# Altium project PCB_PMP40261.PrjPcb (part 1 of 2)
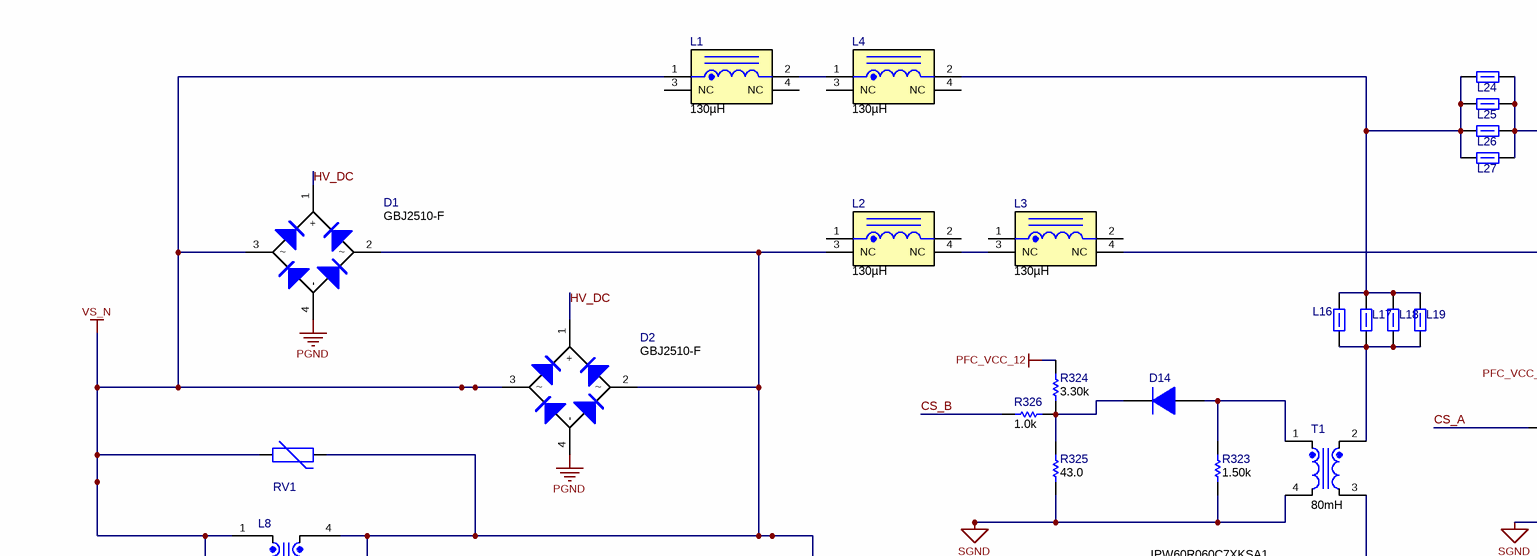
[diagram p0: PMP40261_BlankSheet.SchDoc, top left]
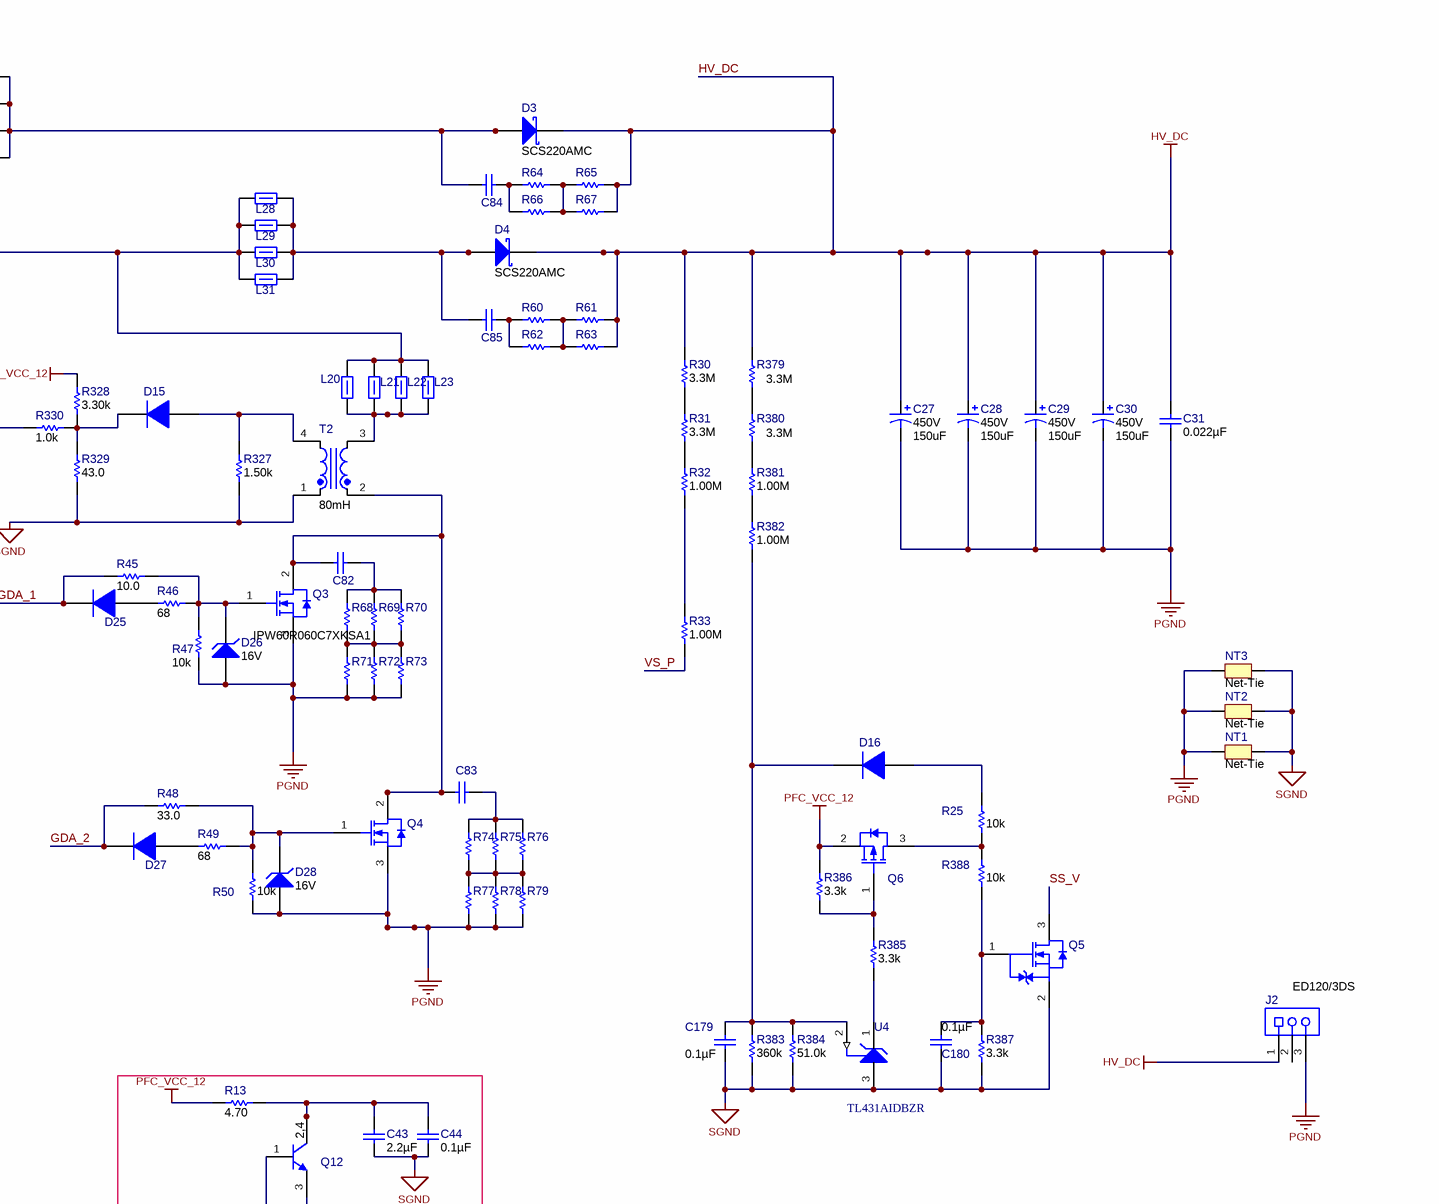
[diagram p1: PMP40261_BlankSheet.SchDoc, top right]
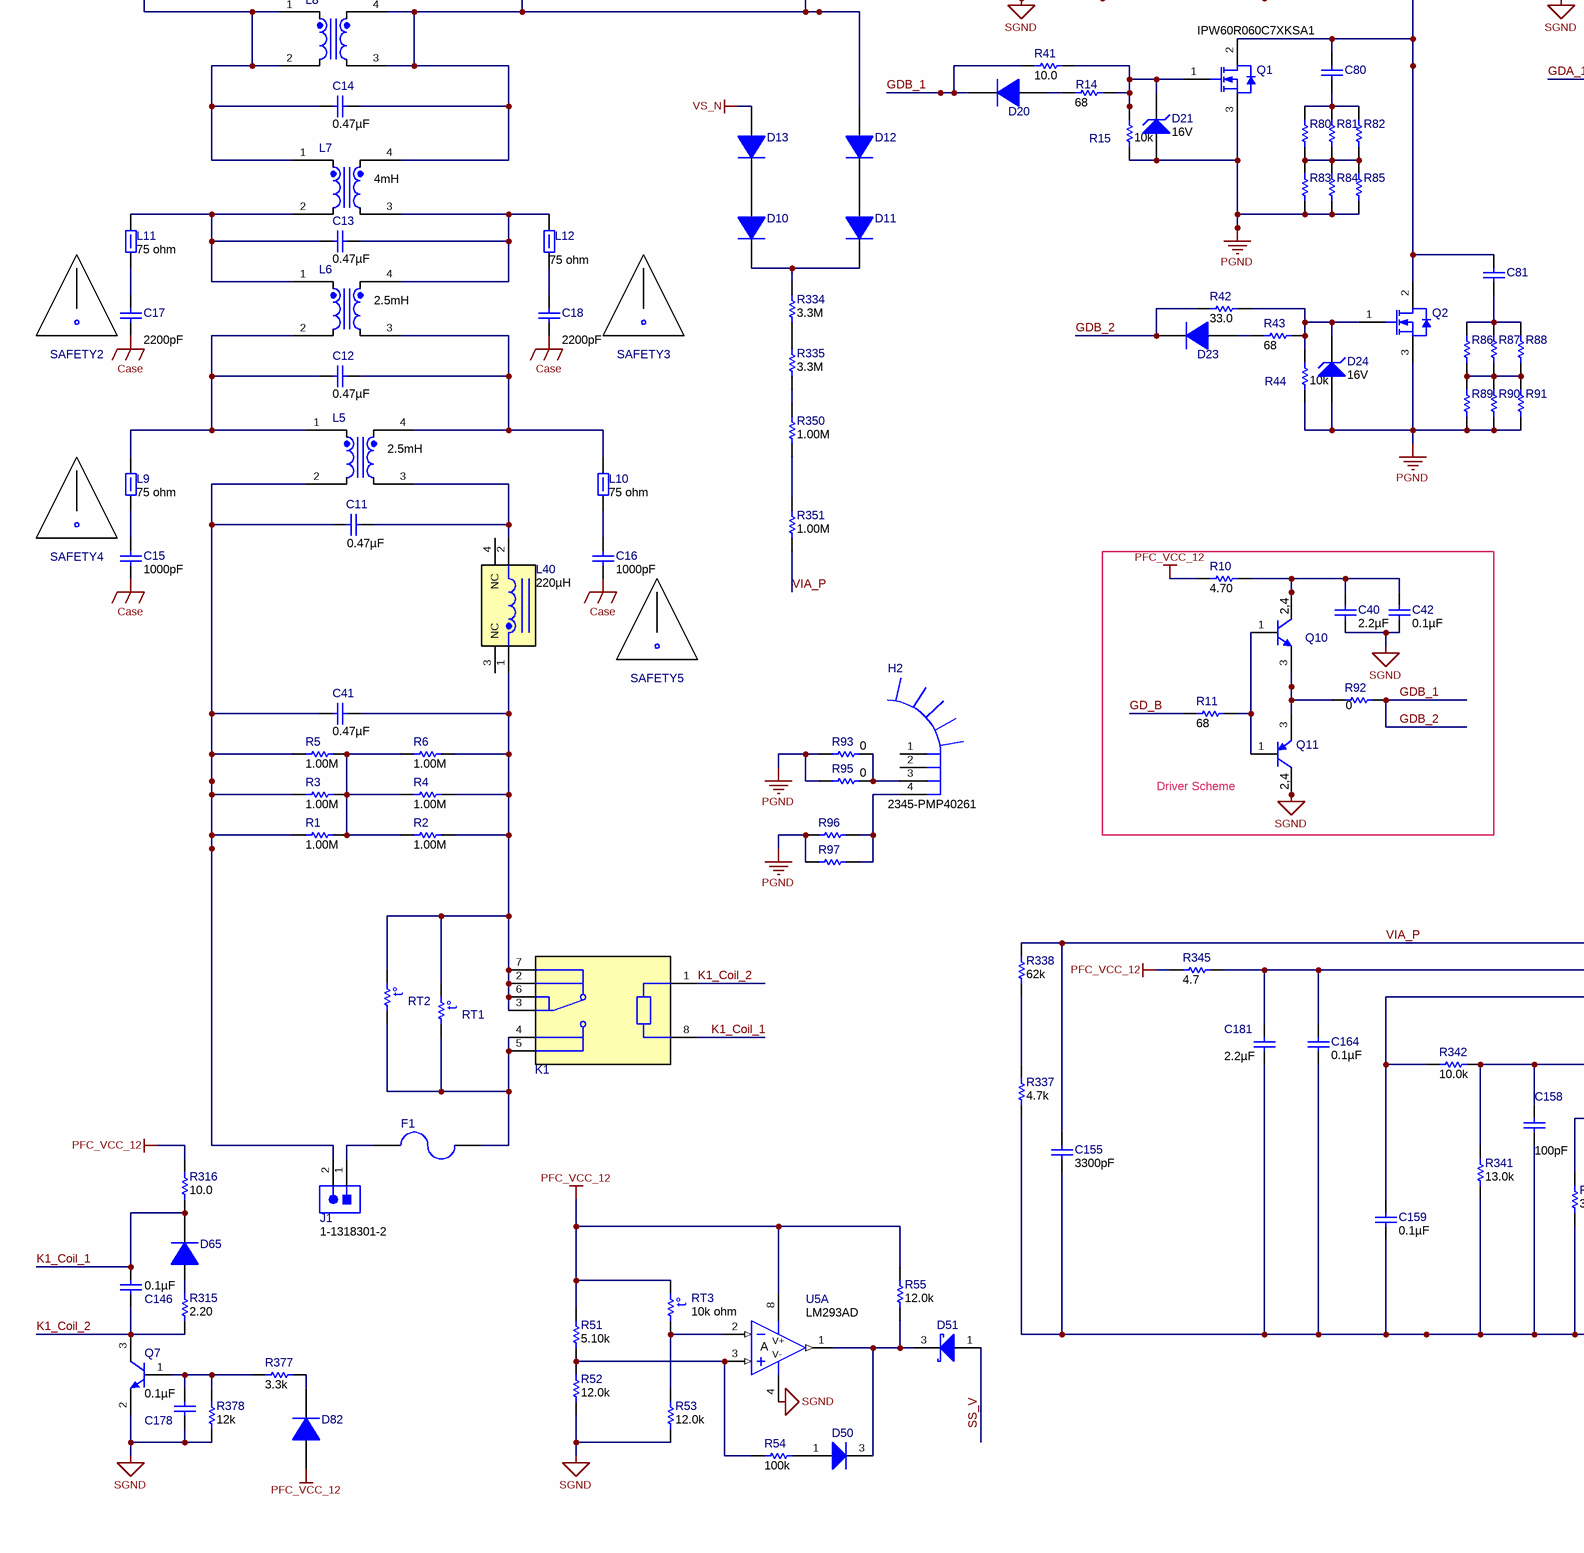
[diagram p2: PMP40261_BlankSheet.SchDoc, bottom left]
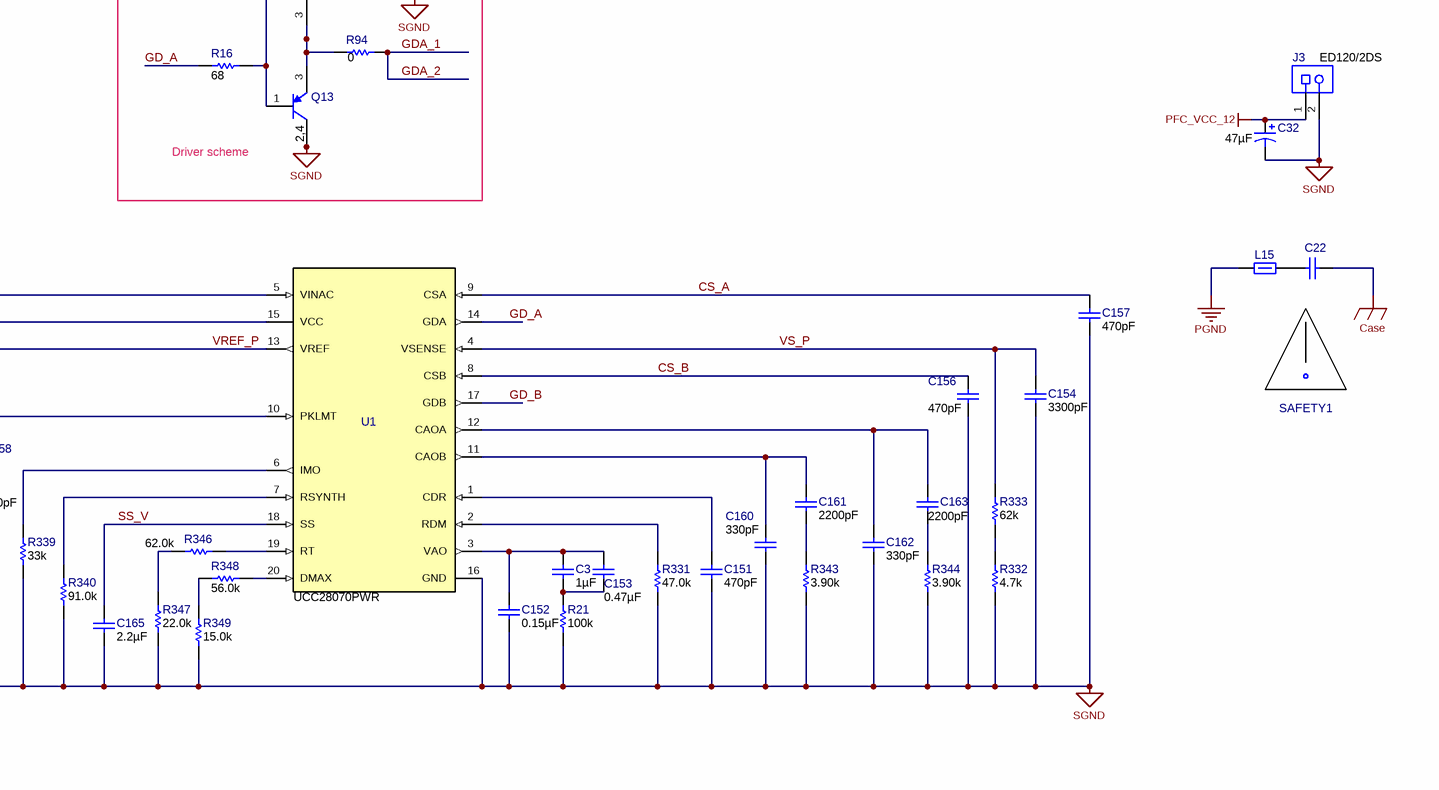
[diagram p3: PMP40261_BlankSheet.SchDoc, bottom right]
CopyrightYear: 2017; PCB_Layout: Who did the Layout?; PCB_Rev: E1; PRJ_Customer: Public Release; PRJ_Engineer: San Chen; PRJ_Number: PMP40261; PRJ_Title: 800W High Efficiency Bridgeless PFC Reference Design; SCH_Rev: E1; TechSupport: http://www.ti.com/support; TID: N/A
1 sheet, 242 parts. Net scope: global (net labels, ports and power ports of the same name join across sheets).
Board file: PMP40261B_pcb.PCBDOC

## Sheet PMP40261_BlankSheet.SchDoc
size A2; Date: Not shown in title block; ApprovedBy: Not shown in title block; CheckedBy: Not shown in title block; Author: Not shown in title block; CompanyName: Not shown in title block; Engineer: San Chen; Organization: Not shown in title block; Address1: Not shown in title block; Address2: Not shown in title block; Address3: Not shown in title block; Address4: Not shown in title block; DocumentNumber: 1; Revision: Use project parameter SCH_Rev; SheetNumber: 1; SheetTotal: 1; PageSetup: Record=PageOptions¦CenterHorizontal=True¦CenterVertical=True¦PrintScale=1.00¦XCorrection=1.00¦YCorrection=1.00¦PrintKind=0¦BorderSize=5000000¦LeftOffset=0¦BottomOffset=0¦Orientation=2¦PaperLength=1000¦PaperWidth=1000¦Scale=100¦PaperSource=15¦PrintQuality=600¦MediaType=1¦DitherType=10¦PaperKind=Letter¦PrintScaleMode=1

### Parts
C3  ValueDisplayed: 1µF  [0603]  (hidden comment: UMK107AB7105KA-T)
C11  ValueDisplayed: 0.47µF  [Kemet_1800x850x1450]  (hidden comment: R46KI347050P0K)
C12  ValueDisplayed: 0.47µF  [Kemet_1800x850x1450]  (hidden comment: R46KI347050P0K)
C13  ValueDisplayed: 0.47µF  [Kemet_1800x850x1450]  (hidden comment: R46KI347050P0K)
C14  ValueDisplayed: 0.47µF  [Kemet_1800x850x1450]  (hidden comment: R46KI347050P0K)
C15  ValueDisplayed: 1000pF  [DE_800x1200x800]  (hidden comment: DE1E3KX102MA5BA01)
C16  ValueDisplayed: 1000pF  [DE_800x1200x800]  (hidden comment: DE1E3KX102MA5BA01)
C17  ValueDisplayed: 2200pF  [CAPRD500W60D800H850]  (hidden comment: DE2E3KY222MA2BM01)
C18  ValueDisplayed: 2200pF  [CAPRD500W60D800H850]  (hidden comment: DE2E3KY222MA2BM01)
C22  DE1B3KX221KN4AP01F  [DE1_87]  (value not drawn)
C27  VDC_V: 450V  ValueDisplayed: 150uF  [BXW_1800x4500_HorizontalDown]  (hidden comment: 450BXW150MEFC18X45)
C28  VDC_V: 450V  ValueDisplayed: 150uF  [BXW_1800x4500_HorizontalDown]  (hidden comment: 450BXW150MEFC18X45)
C29  VDC_V: 450V  ValueDisplayed: 150uF  [BXW_1800x4500_HorizontalDown]  (hidden comment: 450BXW150MEFC18X45)
C30  VDC_V: 450V  ValueDisplayed: 150uF  [BXW_1800x4500_HorizontalDown]  (hidden comment: 450BXW150MEFC18X45)
C31  ValueDisplayed: 0.022µF  [ECWF_L_1250x620x1050]  (hidden comment: ECWF6223JL)
C32  ValueDisplayed: 47µF  [FC_630x1120]  (hidden comment: EEU-FC1V470)
C40  ValueDisplayed: 2.2µF  [0805_HV]  (hidden comment: C2012X7R1H225K125AC)
C41  ValueDisplayed: 0.47µF  [Kemet_1800x850x1450]  (hidden comment: R46KI347050P0K)
C42  ValueDisplayed: 0.1µF  [0603]  (hidden comment: GRM188R71H104KA93D)
C43  ValueDisplayed: 2.2µF  [0805_HV]  (hidden comment: C2012X7R1H225K125AC)
C44  ValueDisplayed: 0.1µF  [0603]  (hidden comment: GRM188R71H104KA93D)
C80  CK45-R3AD101KAGRA  [CK45_600x500x1000]  (value not drawn)
C81  CK45-R3AD101KAGRA  [CK45_600x500x1000]  (value not drawn)
C82  CK45-R3AD101KAGRA  [CK45_600x500x1000]  (value not drawn)
C83  CK45-R3AD101KAGRA  [CK45_600x500x1000]  (value not drawn)
C84  CK45-R3AD101KAGRA  [CK45_600x500x1000]  (value not drawn)
C85  CK45-R3AD101KAGRA  [CK45_600x500x1000]  (value not drawn)
C146  ValueDisplayed: 0.1µF  [0603]  (hidden comment: GRM188R71H104KA93D)
C151  ValueDisplayed: 470pF  [0603]  (hidden comment: 06031C471KAT2A)
C152  ValueDisplayed: 0.15µF  [0603]  (hidden comment: C1608X7R1E154K080AA)
C153  ValueDisplayed: 0.47µF  [0603]  (hidden comment: C1608X7R1H474K080AC)
C154  ValueDisplayed: 3300pF  [0603]  (hidden comment: 06031C332JAT2A)
C155  ValueDisplayed: 3300pF  [0603]  (hidden comment: 06031C332JAT2A)
C156  ValueDisplayed: 470pF  [0603]  (hidden comment: 06031C471JAT2A)
C157  ValueDisplayed: 470pF  [0603]  (hidden comment: 06031C471JAT2A)
C158  ValueDisplayed: 100pF  [0603]  (hidden comment: 0603ZC101KAT2A)
C159  ValueDisplayed: 0.1µF  [0603]  (hidden comment: GRM188R71H104KA93D)
C160  ValueDisplayed: 330pF  [0603]  (hidden comment: C0603C331K5RACTU)
C161  ValueDisplayed: 2200pF  [0603]  (hidden comment: C0603C222K5RACTU)
C162  ValueDisplayed: 330pF  [0603]  (hidden comment: C0603C331K5RACTU)
C163  ValueDisplayed: 2200pF  [0603]  (hidden comment: C0603C222K5RACTU)
C164  ValueDisplayed: 0.1µF  [0603]  (hidden comment: GRM188R71H104KA93D)
C165  ValueDisplayed: 2.2µF  [0805_HV]  (hidden comment: C2012X7R1H225K125AC)
C178  ValueDisplayed: 0.1µF  [0603]  (hidden comment: GRM188R71H104KA93D)
C179  ValueDisplayed: 0.1µF  [0603]  (hidden comment: GRM188R71H104KA93D)
C180  ValueDisplayed: 0.1µF  [0603]  (hidden comment: GRM188R71H104KA93D)
C181  ValueDisplayed: 2.2µF  [0805_HV]  (hidden comment: C2012X7R1H225K125AC)
D1  GBJ2510-F  [GBJ]
D2  GBJ2510-F  [GBJ]
D3  SCS220AMC  [TO-220-2_HORIZ_MH]
D4  SCS220AMC  [TO-220-2_HORIZ_MH]
D10  US1J-13-F  [SMA]  (value not drawn)
D11  US1J-13-F  [SMA]  (value not drawn)
D12  US1J-13-F  [SMA]  (value not drawn)
D13  US1J-13-F  [SMA]  (value not drawn)
D14  RF071M2S  [SOD-123]  (value not drawn)
D15  RF071M2S  [SOD-123]  (value not drawn)
D16  1N4148W-7-F  [SOD-123]  (value not drawn)
D20  1N4148W-7-F  [SOD-123]  (value not drawn)
D21  value 16V  [SOD-123]  (hidden comment: BZT52B16-HE3-08)
D23  1N4148W-7-F  [SOD-123]  (value not drawn)
D24  value 16V  [SOD-123]  (hidden comment: BZT52B16-HE3-08)
D25  1N4148W-7-F  [SOD-123]  (value not drawn)
D26  value 16V  [SOD-123]  (hidden comment: BZT52B16-HE3-08)
D27  1N4148W-7-F  [SOD-123]  (value not drawn)
D28  value 16V  [SOD-123]  (hidden comment: BZT52B16-HE3-08)
D50  BAS16LT1G  [SOT-23]  (value not drawn)
D51  BAT54-7-F  [SOT-23]  (value not drawn)
D65  1N4148W-7-F  [SOD-123]  (value not drawn)
D82  1N4148W-7-F  [SOD-123]  (value not drawn)
F1  HDP500 12A250V  [Fuse_HDP500]  (value not drawn)
H2  2345-PMP40261  [2345-PMP40261]
J1  1-1318301-2  [Amp_1-1318301-2]
J2  ED120/3DS  [On-Shore_ED120_3DS]
J3  ED120/2DS  [On-Shore_ED120_2DS]
K1  G2RL-14-E DC12  [RELAY_G2RL-14-E]  (value not drawn)
L1  ValueDisplayed: 130µH  [CY0239-AL]  (hidden comment: CY0239-BL)
L2  ValueDisplayed: 130µH  [CY0239-AL]  (hidden comment: CY0239-BL)
L3  ValueDisplayed: 130µH  [CY0239-AL]  (hidden comment: CY0239-BL)
L4  ValueDisplayed: 130µH  [CY0239-AL]  (hidden comment: CY0239-BL)
L5  ValueDisplayed: 2.5mH  [Wurth_750343684]  (hidden comment: 750343684)
L6  ValueDisplayed: 2.5mH  [Wurth_750343684]  (hidden comment: 750343684)
L7  ValueDisplayed: 4mH  [Wurth_750343785]  (hidden comment: 7448041104)
L8  0  [Wurth_750343684]  (value not drawn)
L9  ValueDisplayed: 75 ohm  [28L0138]  (hidden comment: 28L0138-10R-10)
L10  ValueDisplayed: 75 ohm  [28L0138]  (hidden comment: 28L0138-10R-10)
L11  ValueDisplayed: 75 ohm  [28L0138]  (hidden comment: 28L0138-10R-10)
L12  ValueDisplayed: 75 ohm  [28L0138]  (hidden comment: 28L0138-10R-10)
L15  28L0138-10R-10  [28L0138]  (value not drawn)
L16  28L0138-10R-10  [28L0138]  (value not drawn)
L17  28L0138-10R-10  [28L0138]  (value not drawn)
L18  28L0138-10R-10  [28L0138]  (value not drawn)
L19  28L0138-10R-10  [28L0138]  (value not drawn)
L20  28L0138-10R-10  [28L0138]  (value not drawn)
L21  28L0138-10R-10  [28L0138]  (value not drawn)
L22  28L0138-10R-10  [28L0138]  (value not drawn)
L23  28L0138-10R-10  [28L0138]  (value not drawn)
L24  28L0138-10R-10  [28L0138]  (value not drawn)
L25  28L0138-10R-10  [28L0138]  (value not drawn)
L26  28L0138-10R-10  [28L0138]  (value not drawn)
L27  28L0138-10R-10  [28L0138]  (value not drawn)
L28  28L0138-10R-10  [28L0138]  (value not drawn)
L29  28L0138-10R-10  [28L0138]  (value not drawn)
L30  28L0138-10R-10  [28L0138]  (value not drawn)
L31  28L0138-10R-10  [28L0138]  (value not drawn)
L40  ValueDisplayed: 220µH  [CY0203-BL]  (hidden comment: CY0203-BL)
NT1  Net-Tie  [Net-Tie_10mil]  (net tie, no BOM)
NT2  Net-Tie  [Net-Tie_10mil]  (net tie, no BOM)
NT3  Net-Tie  [Net-Tie_10mil]  (net tie, no BOM)
Q1  IPW60R060C7XKSA1  [TO-247_Horizontal_Down_1]
Q2  IPW60R060C7XKSA1  [TO-247_Horizontal_Down_1]  (value not drawn)
Q3  IPW60R060C7XKSA1  [TO-247_Horizontal_Down_1]
Q4  IPW60R060C7XKSA1  [TO-247_Horizontal_Down_1]  (value not drawn)
Q5  2N7002K-T1-E3  [SOT-23]  (value not drawn)
Q6  AO3401A  [SOT-23L]  (value not drawn)
Q7  MMBT4401-7-F  [SOT-23]  (value not drawn)
Q10  PBSS4250X,115  [SOT-89-3]  (value not drawn)
Q11  PBSS5250X,115  [SOT-89-3]  (value not drawn)
Q12  PBSS4250X,115  [SOT-89-3]  (value not drawn)
Q13  PBSS5250X,115  [SOT-89-3]  (value not drawn)
R1  ValueDisplayed: 1.00M  [1206]  (hidden comment: CRCW12061M00FKEA)
R2  ValueDisplayed: 1.00M  [1206]  (hidden comment: CRCW12061M00FKEA)
R3  ValueDisplayed: 1.00M  [1206]  (hidden comment: CRCW12061M00FKEA)
R4  ValueDisplayed: 1.00M  [1206]  (hidden comment: CRCW12061M00FKEA)
R5  ValueDisplayed: 1.00M  [1206]  (hidden comment: CRCW12061M00FKEA)
R6  ValueDisplayed: 1.00M  [1206]  (hidden comment: CRCW12061M00FKEA)
R10  ValueDisplayed: 4.70  [1206]  (hidden comment: RC1206FR-074R7L)
R11  ValueDisplayed: 68  [1206]  (hidden comment: CRCW120668R0JNEA)
R13  ValueDisplayed: 4.70  [1206]  (hidden comment: RC1206FR-074R7L)
R14  ValueDisplayed: 68  [1206]  (hidden comment: CRCW120668R0JNEA)
R15  ValueDisplayed: 10k  [0805_HV]  (hidden comment: CRCW080510K0JNEA)
R16  ValueDisplayed: 68  [1206]  (hidden comment: CRCW120668R0JNEA)
R21  ValueDisplayed: 100k  [0603]  (hidden comment: CRCW0603100KFKEA)
R25  ValueDisplayed: 10k  [0805_HV]  (hidden comment: CRCW080510K0JNEA)
R30  ValueDisplayed: 3.3M  [1206]  (hidden comment: RC1206FR-073M3L)
R31  ValueDisplayed: 3.3M  [1206]  (hidden comment: RC1206FR-073M3L)
R32  ValueDisplayed: 1.00M  [1206]  (hidden comment: CRCW12061M00FKEA)
R33  ValueDisplayed: 1.00M  [1206]  (hidden comment: CRCW12061M00FKEA)
R41  ValueDisplayed: 10.0  [1206]  (hidden comment: RC1206FR-0710RL)
R42  ValueDisplayed: 33.0  [1206]  (hidden comment: RC1206FR-0733RL)
R43  ValueDisplayed: 68  [1206]  (hidden comment: CRCW120668R0JNEA)
R44  ValueDisplayed: 10k  [0805_HV]  (hidden comment: CRCW080510K0JNEA)
R45  ValueDisplayed: 10.0  [1206]  (hidden comment: RC1206FR-0710RL)
R46  ValueDisplayed: 68  [1206]  (hidden comment: CRCW120668R0JNEA)
R47  ValueDisplayed: 10k  [0805_HV]  (hidden comment: CRCW080510K0JNEA)
R48  ValueDisplayed: 33.0  [1206]  (hidden comment: RC1206FR-0733RL)
R49  ValueDisplayed: 68  [1206]  (hidden comment: CRCW120668R0JNEA)
R50  ValueDisplayed: 10k  [0805_HV]  (hidden comment: CRCW080510K0JNEA)
R51  ValueDisplayed: 5.10k  [0603]  (hidden comment: RC0603FR-075K1L)
R52  ValueDisplayed: 12.0k  [0603]  (hidden comment: RC0603FR-0712KL)
R53  ValueDisplayed: 12.0k  [0603]  (hidden comment: RC0603FR-0712KL)
R54  ValueDisplayed: 100k  [0603]  (hidden comment: CRCW0603100KFKEA)
R55  ValueDisplayed: 12.0k  [0603]  (hidden comment: RC0603FR-0712KL)
R60  ERJ-8ENF39R0V  [1206]  (value not drawn)
R61  ERJ-8ENF39R0V  [1206]  (value not drawn)
R62  ERJ-8ENF39R0V  [1206]  (value not drawn)
R63  ERJ-8ENF39R0V  [1206]  (value not drawn)
R64  ERJ-8ENF39R0V  [1206]  (value not drawn)
R65  ERJ-8ENF39R0V  [1206]  (value not drawn)
R66  ERJ-8ENF39R0V  [1206]  (value not drawn)
R67  ERJ-8ENF39R0V  [1206]  (value not drawn)
R68  ERJ-8ENF39R0V  [1206]  (value not drawn)
R69  ERJ-8ENF39R0V  [1206]  (value not drawn)
R70  ERJ-8ENF39R0V  [1206]  (value not drawn)
R71  ERJ-8ENF39R0V  [1206]  (value not drawn)
R72  ERJ-8ENF39R0V  [1206]  (value not drawn)
R73  ERJ-8ENF39R0V  [1206]  (value not drawn)
R74  ERJ-8ENF39R0V  [1206]  (value not drawn)
R75  ERJ-8ENF39R0V  [1206]  (value not drawn)
R76  ERJ-8ENF39R0V  [1206]  (value not drawn)
R77  ERJ-8ENF39R0V  [1206]  (value not drawn)
R78  ERJ-8ENF39R0V  [1206]  (value not drawn)
R79  ERJ-8ENF39R0V  [1206]  (value not drawn)
R80  ERJ-8ENF39R0V  [1206]  (value not drawn)
R81  ERJ-8ENF39R0V  [1206]  (value not drawn)
R82  ERJ-8ENF39R0V  [1206]  (value not drawn)
R83  ERJ-8ENF39R0V  [1206]  (value not drawn)
R84  ERJ-8ENF39R0V  [1206]  (value not drawn)
R85  ERJ-8ENF39R0V  [1206]  (value not drawn)
R86  ERJ-8ENF39R0V  [1206]  (value not drawn)
R87  ERJ-8ENF39R0V  [1206]  (value not drawn)
R88  ERJ-8ENF39R0V  [1206]  (value not drawn)
R89  ERJ-8ENF39R0V  [1206]  (value not drawn)
R90  ERJ-8ENF39R0V  [1206]  (value not drawn)
R91  ERJ-8ENF39R0V  [1206]  (value not drawn)
R92  ValueDisplayed: 0  [5108]  (hidden comment: 5108)
R93  ValueDisplayed: 0  [5108]  (hidden comment: 5108)
R94  ValueDisplayed: 0  [5108]  (hidden comment: 5108)
R95  ValueDisplayed: 0  [5108]  (hidden comment: 5108)
R96  5108  [5108]  (value not drawn)
R97  5108  [5108]  (value not drawn)
R315  ValueDisplayed: 2.20  [1206]  (hidden comment: RC1206FR-072R2L)
R316  ValueDisplayed: 10.0  [1206]  (hidden comment: RC1206FR-0710RL)
R323  ValueDisplayed: 1.50k  [1206]  (hidden comment: CRCW12061K50FKEA)
R324  ValueDisplayed: 3.30k  [0603]  (hidden comment: RC0603FR-073K3L)
R325  ValueDisplayed: 43.0  [1206]  (hidden comment: RC1206FR-0743RL)
R326  ValueDisplayed: 1.0k  [0805_HV]  (hidden comment: CRCW08051K00JNEA)
R327  ValueDisplayed: 1.50k  [1206]  (hidden comment: CRCW12061K50FKEA)
R328  ValueDisplayed: 3.30k  [0603]  (hidden comment: RC0603FR-073K3L)
R329  ValueDisplayed: 43.0  [1206]  (hidden comment: RC1206FR-0743RL)
R330  ValueDisplayed: 1.0k  [0805_HV]  (hidden comment: CRCW08051K00JNEA)
R331  ValueDisplayed: 47.0k  [0603]  (hidden comment: CRCW060347K0FKEA)
R332  ValueDisplayed: 4.7k  [0805_HV]  (hidden comment: KTR10EZPF4701)
R333  ValueDisplayed: 62k  [0805_HV]  (hidden comment: KTR10EZPF6202)
R334  ValueDisplayed: 3.3M  [1206]  (hidden comment: RC1206FR-073M3L)
R335  ValueDisplayed: 3.3M  [1206]  (hidden comment: RC1206FR-073M3L)
R337  ValueDisplayed: 4.7k  [0805_HV]  (hidden comment: KTR10EZPF4701)
R338  ValueDisplayed: 62k  [0805_HV]  (hidden comment: KTR10EZPF6202)
R339  ValueDisplayed: 33k  [0603]  (hidden comment: RC0603FR-0724KL)
R340  ValueDisplayed: 91.0k  [0603]  (hidden comment: RC0603FR-0791KL)
R341  ValueDisplayed: 13.0k  [0603]  (hidden comment: CRCW060313K0FKEA)
R342  ValueDisplayed: 10.0k  [0603]  (hidden comment: CRCW060310K0FKEA)
R343  ValueDisplayed: 3.90k  [0603]  (hidden comment: CRCW06033K90FKEA)
R344  ValueDisplayed: 3.90k  [0603]  (hidden comment: CRCW06033K90FKEA)
R345  ValueDisplayed: 4.7  [0805_HV]  (hidden comment: CRCW08054R70JNEA)
R346  ValueDisplayed: 62.0k  [0603]  (hidden comment: RC0603FR-0762KL)
R347  ValueDisplayed: 22.0k  [0603]  (hidden comment: ERJ-3EKF2202V)
R348  ValueDisplayed: 56.0k  [0603]  (hidden comment: RG1608P-563-B-T5)
R349  ValueDisplayed: 15.0k  [0603]  (hidden comment: CRCW060315K0FKEA)
R350  ValueDisplayed: 1.00M  [1206]  (hidden comment: CRCW12061M00FKEA)
R351  ValueDisplayed: 1.00M  [1206]  (hidden comment: CRCW12061M00FKEA)
R377  ValueDisplayed: 3.3k  [0805_HV]  (hidden comment: ERJ-6GEYJ332V)
R378  ValueDisplayed: 12k  [0805_HV]  (hidden comment: CRCW080512K0JNEA)
R379  ValueDisplayed: 3.3M  [1206]  (hidden comment: RC1206FR-073M3L)
R380  ValueDisplayed: 3.3M  [1206]  (hidden comment: RC1206FR-073M3L)
R381  ValueDisplayed: 1.00M  [1206]  (hidden comment: CRCW12061M00FKEA)
R382  ValueDisplayed: 1.00M  [1206]  (hidden comment: CRCW12061M00FKEA)
R383  ValueDisplayed: 360k  [0805_HV]  (hidden comment: CRCW0805360KJNEA)
R384  ValueDisplayed: 51.0k  [1206]  (hidden comment: RC1206FR-0751KL)
R385  ValueDisplayed: 3.3k  [0805_HV]  (hidden comment: ERJ-6GEYJ332V)
R386  ValueDisplayed: 3.3k  [0805_HV]  (hidden comment: ERJ-6GEYJ332V)
R387  ValueDisplayed: 3.3k  [0805_HV]  (hidden comment: ERJ-6GEYJ332V)
R388  ValueDisplayed: 10k  [0805_HV]  (hidden comment: CRCW080510K0JNEA)
RT1  SCK205R0MSBY502  [SCK20_S]  (value not drawn)
RT2  SCK205R0MSBY502  [SCK20_S]  (value not drawn)
RT3  value 10k ohm  [0603]  (hidden comment: NCP18XH103J03RB)
RV1  B72214S0421K101  [TDK_B72214S0421]  (value not drawn)
T1  ValueDisplayed: 80mH  [XFMR_CS4200V-01L]  (hidden comment: CS4200V-01L)
T2  ValueDisplayed: 80mH  [XFMR_CS4200V-01L]  (hidden comment: CS4200V-01L)
U1  UCC28070PWR  [PW0020A_N]
U4  TL431AIDBZR  [DBZ0003A_N]
U5  LM293AD  [D0008A_N]  (part A of 2)

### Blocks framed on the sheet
Driver Scheme: C40 C42 Q10 Q11 R10 R11 R92
Driver scheme: C43 C44 Q12 Q13 R13 R16 R94

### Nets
Case: C15.2 C16.2 C17.2 C18.2 C22.2
HV_DC: C27.1(+) C28.1(+) C29.1(+) C30.1(+) C31.1 D1.1(+) D2.1(+) D3.1(K) D4.1(K) J2.1 R30.2 R61.1 R63.1 R65.1 R67.1 R379.2
PFC_VCC_12: C32.1(+) D82.2(A) J3.1 Q6.2(S) R10.1 R13.1 R51.2 R55.2 R316.2 R324.2 R328.2 R345.1 R386.2 RT3.2 U5.8(V+)
PGND: C27.2(-) C28.2(-) C29.2(-) C30.2(-) C31.2 D1.4(-) D2.4(-) D21.2(A) D24.2(A) D26.2(A) D28.2(A) J2.3 L15.2 NT1.1 NT2.1 NT3.1 Q1.3(S) Q2.3(S) Q3.3(S) Q4.3(S) R15.2 R44.2 R47.2 R50.2 R71.2 R72.2 R73.2 R77.2 R78.2 R79.2 R83.2 R84.2 R85.2 R89.2 R90.2 R91.2 R93.1 R95.1 R96.1 R97.1
SGND: C32.2(-) C40.2 C42.2 C43.2 C44.2 C151.2 C152.2 C154.2 C155.2 C156.2 C157.2 C158.2 C159.2 C160.2 C162.2 C164.2 C165.2 C178.2 C179.2 C180.2 C181.2 J3.2 NT1.2 NT2.2 NT3.2 Q5.2(S) Q7.2(E) Q11.2(C) Q11.4(C) Q13.2(C) Q13.4(C) R21.1 R52.1 R53.1 R323.1 R325.1 R327.1 R329.1 R331.1 R332.1 R337.1 R339.1 R340.1 R341.2 R343.1 R344.1 R347.1 R349.1 R378.1 R383.1 R384.1 R387.1 T1.4 T2.1 U1.16(GND) U4.3(ANODE) U5.4(V-)
VS_N: C14.1 D1.3 D2.3 D13.2(A) L1.1 L7.1 L8.1 L8.2 RV1.1
CS_A: C157.1 R330.2 U1.9(CSA)
CS_B: C156.1 R326.2 U1.8(CSB)
GD_A: R16.1 U1.14(GDA)
GD_B: R11.1 U1.17(GDB)
GDA_1: D25.1(K) D27.1(K) R45.1 R48.1 R94.2  [also labelled GDA_2]
GDB_1: D20.1(K) D23.1(K) R41.1 R42.1 R92.2  [also labelled GDB_2]
K1_Coil_1: C146.1 D65.1(K) K1.8 R316.1
K1_Coil_2: C146.2 K1.1 Q7.3(C) R315.1
SS_V: C165.1 D51.1(A) Q5.3(D) U1.18(SS)
VIA_P: C155.1 R338.2 R351.1 U1.5(VINAC)
VREF_P: C159.1 R342.1 U1.13(VREF)
VS_P: C154.1 R33.1 R333.2 U1.4(VSENSE)
NetC3_1: C3.1 C152.1 C153.1 U1.3(VAO)
NetC3_2: C3.2 C153.2 R21.2
NetC11_1: C11.1 C41.1 J1.2 L5.2 R1.2 R3.2 R5.2
NetC11_2: C11.2 L5.3 L40.2
NetC12_1: C12.1 L5.1 L6.2 L9.2
NetC12_2: C12.2 L5.4 L6.3 L10.2
NetC13_1: C13.1 L6.1 L7.2 L11.2
NetC13_2: C13.2 L6.4 L7.3 L12.2
NetC14_2: C14.2 D1.2 D2.2 D12.2(A) L2.3(NC) L7.4 L8.3 L8.4 RV1.2
NetC15_1: C15.1 L9.1
NetC16_1: C16.1 L10.1
NetC17_1: C17.1 L11.1
NetC18_1: C18.1 L12.1
NetC22_1: C22.1 L15.1
NetC40_1: C40.1 C42.1 Q10.2(C) Q10.4(C) R10.2
NetC41_2: C41.2 K1.2 K1.3 K1.6 K1.7 L40.1 R2.1 R4.1 R6.1 RT1.2 RT2.2
NetC43_1: C43.1 C44.1 Q12.2(C) Q12.4(C) R13.2
NetC80_1: C80.1 C81.1 Q1.2(D) Q2.2(D) T1.3
NetC80_2: C80.2 R80.1 R81.1 R82.1
NetC81_2: C81.2 R86.1 R87.1 R88.1
NetC82_1: C82.1 C83.1 Q3.2(D) Q4.2(D) T2.2
NetC82_2: C82.2 R68.1 R69.1 R70.1
NetC83_2: C83.2 R74.1 R75.1 R76.1
NetC84_1: C84.1 D3.2(A) L24.1 L25.1 L26.1 L27.1
NetC84_2: C84.2 R64.2 R66.2
NetC85_1: C85.1 D4.2(A) L28.1 L29.1 L30.1 L31.1
NetC85_2: C85.2 R60.2 R62.2
NetC151_1: C151.1 U1.1(CDR)
NetC158_1: C158.1 R341.1 R342.2 U1.10(PKLMT)
NetC160_1: C160.1 C161.1 U1.11(CAOB)
NetC161_2: C161.2 R343.2
NetC162_1: C162.1 C163.1 U1.12(CAOA)
NetC163_2: C163.2 R344.2
NetC164_1: C164.1 C181.1 R345.2 U1.15(VCC)
NetC178_1: C178.1 Q7.1(B) R377.1 R378.2
NetC179_1: C179.1 D16.1(K) R382.1 R383.2 R384.2 U4.2(REF)
NetC180_1: C180.1 Q5.1(G) R387.2 R388.2
NetD10_1: D10.1(K) D11.1(K) R334.2
NetD10_2: D10.2(A) D13.1(K)
NetD11_2: D11.2(A) D12.1(K)
NetD14_1: D14.1(K) R324.1 R325.2 R326.1
NetD14_2: D14.2(A) R323.2 T1.1
NetD15_1: D15.1(K) R328.1 R329.2 R330.1
NetD15_2: D15.2(A) R327.2 T2.4
NetD16_2: D16.2(A) R25.1
NetD20_2: D20.2(A) R14.1
NetD21_1: D21.1(K) Q1.1(G) R14.2 R15.1 R41.2
NetD23_2: D23.2(A) R43.1
NetD24_1: D24.1(K) Q2.1(G) R42.2 R43.2 R44.1
NetD25_2: D25.2(A) R46.1
NetD26_1: D26.1(K) Q3.1(G) R45.2 R46.2 R47.1
NetD27_2: D27.2(A) R49.1
NetD28_1: D28.1(K) Q4.1(G) R48.2 R49.2 R50.1
NetD50_1: D50.1(A) R54.1
NetD50_3: D50.3(K) D51.3(K) R55.1 U5.1(OUT)
NetD65_2: D65.2(A) R315.2
NetD82_1: D82.1(K) R377.2
NetF1_1: F1.1 K1.4 K1.5 RT1.1 RT2.1
NetF1_2: F1.2 J1.1
NetH2_3: H2.3 R93.2 R95.2
NetH2_4: H2.4 R96.2 R97.2
NetL1_2: L1.2 L4.1
NetL2_4: L2.4(NC) L3.3(NC)
NetL3_4: L3.4(NC) L20.2 L21.2 L22.2 L23.2 L28.2 L29.2 L30.2 L31.2
NetL4_2: L4.2 L16.2 L17.2 L18.2 L19.2 L24.2 L25.2 L26.2 L27.2
NetL16_1: L16.1 L17.1 L18.1 L19.1 T1.2
NetL20_1: L20.1 L21.1 L22.1 L23.1 T2.3
NetQ6_1: Q6.1(G) R385.2 R386.1
NetQ6_3: Q6.3(D) R25.2 R388.1
NetQ10_1: Q10.1(B) Q11.1(B) R11.2
NetQ10_3: Q10.3(E) Q11.3(E) R92.1
NetQ12_1: Q12.1(B) Q13.1(B) R16.2
NetQ12_3: Q12.3(E) Q13.3(E) R94.1
NetR1_1: R1.1 R2.2 R3.1 R4.2 R5.1 R6.2
NetR30_1: R30.1 R31.2
NetR31_1: R31.1 R32.2
NetR32_1: R32.1 R33.2
NetR51_1: R51.1 R52.2 R54.2 U5.3(IN+)
NetR53_2: R53.2 RT3.1 U5.2(IN-)
NetR60_1: R60.1 R61.2 R62.1 R63.2
NetR64_1: R64.1 R65.2 R66.1 R67.2
NetR68_2: R68.2 R69.2 R70.2 R71.1 R72.1 R73.1
NetR74_2: R74.2 R75.2 R76.2 R77.1 R78.1 R79.1
NetR80_2: R80.2 R81.2 R82.2 R83.1 R84.1 R85.1
NetR86_2: R86.2 R87.2 R88.2 R89.1 R90.1 R91.1
NetR331_2: R331.2 U1.2(RDM)
NetR332_2: R332.2 R333.1
NetR334_1: R334.1 R335.2
NetR335_1: R335.1 R350.2
NetR337_2: R337.2 R338.1
NetR339_2: R339.2 U1.6(IMO)
NetR340_2: R340.2 U1.7(RSYNTH)
NetR346_1: R346.1 U1.19(RT)
NetR346_2: R346.2 R347.2
NetR348_1: R348.1 R349.2
NetR348_2: R348.2 U1.20(DMAX)
NetR350_1: R350.1 R351.2
NetR379_1: R379.1 R380.2
NetR380_1: R380.1 R381.2
NetR381_1: R381.1 R382.2
NetR385_1: R385.1 U4.1(CATHODE)

Not connected (* = marked no-connect by the designer): H2 1 2; J2 2; L1 3(NC) 4(NC); L2 1 2; L3 1 2; L4 3(NC) 4(NC); L40 3(NC) 4(NC)

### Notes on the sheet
- (near C17) SAFETY2
- SAFETY3
- (near C15) SAFETY4
- SAFETY5
- SAFETY1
